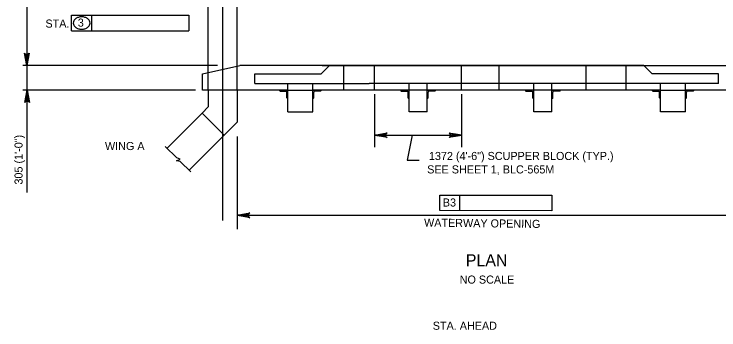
# Model space of a CAD drawing. Extents: x 638268 to 640277, y 295465 to 298435.
# Drawn here: x 638489.1 to 638751, y 297540.7 to 297658 of the extents above; entities that cross this region are included whole.
import ezdxf

# ---------------------------------------------------------------- set-up
doc = ezdxf.new("R2010")
doc.units = 0
for name, color, linetype in [('2', 7, 'Continuous'), ('3', 7, 'Continuous'), ('4', 7, 'Continuous')]:
    doc.layers.add(name, color=color, linetype=linetype)

msp = doc.modelspace()

# ---------------------------------------------------------------- linework, layer by layer
at = {"layer": '2'}
for p, q in [((638561.24, 297629.77), (638561.24, 297741.89)), ((638572.01, 297629.77), (638572.01, 297741.89)), ((638559.11, 297635.8), (638572.96, 297638.9)), ((638606.26, 297638.9), (638572.96, 297638.9)), ((638606.26, 297638.9), (638603.17, 297635.8)), ((638603.59, 297638.9), (638619.75, 297638.9)), ((638603.59, 297638.9), (638756.47, 297638.9)), ((638723.16, 297638.9), (638606.26, 297638.9)), ((638611.64, 297629.77), (638611.64, 297638.9)), ((638623.04, 297629.77), (638623.04, 297638.9)), ((638655.38, 297629.77), (638655.38, 297638.9)), ((638669.41, 297629.77), (638669.41, 297638.9)), ((638701.75, 297629.77), (638701.75, 297638.9)), ((638716.53, 297629.77), (638716.53, 297638.9)), ((638723.16, 297638.9), (638726.25, 297635.8)), ((638559.11, 297629.77), (638559.11, 297635.8)), ((638578.53, 297635.8), (638603.17, 297635.8)), ((638578.53, 297632.17), (638578.53, 297635.8)), ((638750.89, 297635.8), (638726.25, 297635.8)), ((638750.89, 297632.17), (638750.89, 297635.8)), ((638578.53, 297632.17), (638621.04, 297632.17)), ((638590.86, 297621.68), (638590.86, 297632.17)), ((638600.09, 297621.68), (638600.09, 297632.17)), ((638750.89, 297632.17), (638621.04, 297632.17)), ((638635.85, 297621.68), (638635.85, 297632.17)), ((638642.58, 297621.68), (638642.58, 297632.17)), ((638682.21, 297621.68), (638682.21, 297632.17)), ((638688.94, 297621.68), (638688.94, 297632.17)), ((638729.33, 297621.68), (638729.33, 297632.17)), ((638738.57, 297621.68), (638738.57, 297632.17)), ((638590.86, 297629.77), (638559.11, 297629.77)), ((638561.24, 297629.77), (638561.24, 297623.56)), ((638572.01, 297629.77), (638572.01, 297617.86)), ((638587.76, 297629.59), (638587.76, 297629.77)), ((638590.86, 297629.77), (638587.76, 297629.77)), ((638587.95, 297629.41), (638590.13, 297629.41)), ((638590.49, 297626.86), (638590.49, 297629.05)), ((638590.86, 297629.77), (638600.09, 297629.77)), ((638590.86, 297626.68), (638590.86, 297629.77)), ((638600.09, 297626.68), (638600.09, 297629.77)), ((638600.09, 297629.77), (638603.18, 297629.77)), ((638635.85, 297629.77), (638600.09, 297629.77)), ((638600.46, 297626.86), (638600.46, 297629.05)), ((638603, 297629.41), (638600.82, 297629.41)), ((638603.18, 297629.59), (638603.18, 297629.77)), ((638632.76, 297629.59), (638632.76, 297629.77)), ((638635.85, 297629.77), (638632.76, 297629.77)), ((638632.94, 297629.41), (638635.12, 297629.41)), ((638635.49, 297626.86), (638635.49, 297629.05)), ((638635.85, 297626.68), (638635.85, 297629.77)), ((638642.58, 297629.77), (638635.85, 297629.77)), ((638642.58, 297626.68), (638642.58, 297629.77)), ((638642.58, 297629.77), (638645.67, 297629.77)), ((638681, 297629.77), (638642.58, 297629.77)), ((638681, 297629.77), (638642.58, 297629.77)), ((638642.94, 297626.86), (638642.94, 297629.05)), ((638645.49, 297629.41), (638643.3, 297629.41)), ((638645.67, 297629.59), (638645.67, 297629.77)), ((638679.12, 297629.59), (638679.12, 297629.77)), ((638682.21, 297629.77), (638679.12, 297629.77)), ((638679.3, 297629.41), (638681.49, 297629.41)), ((638690.19, 297629.77), (638680.96, 297629.77)), ((638681.85, 297626.86), (638681.85, 297629.05)), ((638688.94, 297629.77), (638682.21, 297629.77)), ((638682.21, 297626.68), (638682.21, 297629.77)), ((638688.94, 297626.68), (638688.94, 297629.77)), ((638688.94, 297629.77), (638692.03, 297629.77)), ((638727.37, 297629.77), (638688.94, 297629.77)), ((638689.3, 297626.86), (638689.3, 297629.05)), ((638691.85, 297629.41), (638689.67, 297629.41)), ((638692.03, 297629.59), (638692.03, 297629.77)), ((638726.24, 297629.59), (638726.24, 297629.77)), ((638729.33, 297629.77), (638726.24, 297629.77)), ((638726.42, 297629.41), (638728.61, 297629.41)), ((638728.97, 297626.86), (638728.97, 297629.05)), ((638729.33, 297626.68), (638729.33, 297629.77)), ((638729.33, 297629.77), (638738.57, 297629.77)), ((638738.57, 297626.68), (638738.57, 297629.77)), ((638738.57, 297629.77), (638741.66, 297629.77)), ((638770.31, 297629.77), (638738.57, 297629.77)), ((638738.93, 297626.86), (638738.93, 297629.05)), ((638741.48, 297629.41), (638739.3, 297629.41)), ((638741.66, 297629.59), (638741.66, 297629.77)), ((638590.67, 297626.68), (638590.86, 297626.68)), ((638600.27, 297626.68), (638600.09, 297626.68)), ((638635.67, 297626.68), (638635.85, 297626.68)), ((638642.76, 297626.68), (638642.58, 297626.68)), ((638682.03, 297626.68), (638682.21, 297626.68)), ((638689.12, 297626.68), (638688.94, 297626.68)), ((638729.15, 297626.68), (638729.33, 297626.68)), ((638738.75, 297626.68), (638738.57, 297626.68)), ((638561.24, 297623.56), (638558.93, 297621.25)), ((638558.93, 297621.25), (638545.91, 297608.23)), ((638558.93, 297621.25), (638567.16, 297613.02)), ((638590.86, 297621.68), (638600.09, 297621.68)), ((638642.58, 297621.68), (638635.85, 297621.68)), ((638688.94, 297621.68), (638682.21, 297621.68)), ((638688.94, 297621.68), (638682.21, 297621.68)), ((638738.57, 297621.68), (638729.33, 297621.68)), ((638572.01, 297617.86), (638554.14, 297600))]:
    msp.add_line(p, q, dxfattribs=at)
for centre, radius, start, end in [((638587.95, 297629.59), 0.182, 180.0016, 270), ((638590.13, 297629.05), 0.364, 0.0016, 90), ((638600.82, 297629.05), 0.364, 90, 179.9984), ((638603, 297629.59), 0.182, 270, 359.9984), ((638632.94, 297629.59), 0.182, 180.0016, 270), ((638635.12, 297629.05), 0.364, 0.0016, 90), ((638643.3, 297629.05), 0.364, 90, 179.9984), ((638645.49, 297629.59), 0.182, 270, 359.9984), ((638679.3, 297629.59), 0.182, 180.0016, 270), ((638681.49, 297629.05), 0.364, 0.0016, 90), ((638689.67, 297629.05), 0.364, 90, 179.9984), ((638691.85, 297629.59), 0.182, 270, 359.9984), ((638726.42, 297629.59), 0.182, 180.0016, 270), ((638728.61, 297629.05), 0.364, 0.0016, 90), ((638739.3, 297629.05), 0.364, 90, 179.9984), ((638741.48, 297629.59), 0.182, 270, 359.9984), ((638590.67, 297626.86), 0.182, 180.0016, 270), ((638600.27, 297626.86), 0.182, 270, 359.9984), ((638635.67, 297626.86), 0.182, 180.0016, 270), ((638642.76, 297626.86), 0.182, 270, 359.9984), ((638682.03, 297626.86), 0.182, 180.0016, 270), ((638689.12, 297626.86), 0.182, 270, 359.9984), ((638729.15, 297626.86), 0.182, 180.0016, 270), ((638738.75, 297626.86), 0.182, 270, 359.9984)]:
    msp.add_arc(centre, radius, start, end, dxfattribs=at)
at = {"layer": '3'}
for p, q in [((638566.62, 297581.37), (638566.62, 297801.29)), ((638545.27, 297608.86), (638549.54, 297604.59)), ((638549.46, 297603.48), (638550.85, 297604.18)), ((638550.85, 297604.18), (638549.54, 297604.59)), ((638550.81, 297603.32), (638549.46, 297603.48)), ((638550.81, 297603.32), (638554.72, 297599.41))]:
    msp.add_line(p, q, dxfattribs=at)
at = {"layer": '4'}
for p, q in [((638493.78, 297781.29), (638493.78, 297591.81)), ((638510.4, 297651.84), (638510.4, 297657.61)), ((638510.4, 297657.61), (638517.97, 297657.61)), ((638517.97, 297651.84), (638517.97, 297657.61)), ((638517.97, 297657.61), (638553.98, 297657.61)), ((638553.98, 297657.61), (638553.98, 297651.84)), ((638510.4, 297651.84), (638553.98, 297651.84)), ((638564.62, 297638.89), (638492.34, 297638.89)), ((638556.55, 297629.77), (638492.34, 297629.77)), ((638623.04, 297628.24), (638623.04, 297608.6)), ((638655.38, 297628.24), (638655.38, 297608.6)), ((638572.01, 297612.54), (638572.01, 297578.12)), ((638623.04, 297613.03), (638655.38, 297613.03)), ((638637, 297613.03), (638635.15, 297603.8)), ((638635.15, 297603.8), (638639.58, 297603.8)), ((638647.35, 297590.79), (638654.7, 297590.79)), ((638647.35, 297585.03), (638647.35, 297590.79)), ((638654.7, 297585.02), (638654.7, 297590.79)), ((638654.7, 297590.79), (638688.87, 297590.77)), ((638688.87, 297590.77), (638688.87, 297585)), ((638572.01, 297583.28), (638757, 297583.28)), ((638688.87, 297585), (638647.35, 297585.03))]:
    msp.add_line(p, q, dxfattribs=at)
for points in [[(638493.78, 297638.89), (638492.9, 297643.55), (638493.15, 297643.2), (638493.46, 297643.01), (638493.78, 297642.96), (638494.09, 297643.01), (638494.4, 297643.2), (638494.65, 297643.55), (638493.78, 297638.89), (638494.4, 297643.2), (638494.09, 297643.01), (638493.78, 297638.89), (638493.78, 297642.96), (638493.46, 297643.01), (638493.78, 297638.89), (638493.15, 297643.2)], [(638493.89, 297629.77), (638494.76, 297625.11), (638494.51, 297625.47), (638494.2, 297625.66), (638493.89, 297625.71), (638493.57, 297625.66), (638493.26, 297625.47), (638493.01, 297625.11), (638493.89, 297629.77), (638493.26, 297625.47), (638493.57, 297625.66), (638493.89, 297629.77), (638493.89, 297625.71), (638494.2, 297625.66), (638493.89, 297629.77), (638494.51, 297625.47)], [(638623.04, 297613.03), (638627.7, 297613.9), (638627.35, 297613.65), (638627.16, 297613.34), (638627.11, 297613.03), (638627.16, 297612.72), (638627.35, 297612.4), (638627.7, 297612.16), (638623.04, 297613.03), (638627.35, 297612.4), (638627.16, 297612.72), (638623.04, 297613.03), (638627.11, 297613.03), (638627.16, 297613.34), (638623.04, 297613.03), (638627.35, 297613.65)], [(638655.38, 297613.03), (638650.72, 297612.16), (638651.08, 297612.4), (638651.27, 297612.72), (638651.32, 297613.03), (638651.27, 297613.34), (638651.08, 297613.65), (638650.72, 297613.9), (638655.38, 297613.03), (638651.08, 297613.65), (638651.27, 297613.34), (638655.38, 297613.03), (638651.32, 297613.03), (638651.27, 297612.72), (638655.38, 297613.03), (638651.08, 297612.4)], [(638572.01, 297583.28), (638576.67, 297584.15), (638576.31, 297583.9), (638576.12, 297583.59), (638576.07, 297583.28), (638576.12, 297582.96), (638576.31, 297582.65), (638576.67, 297582.4), (638572.01, 297583.28), (638576.31, 297582.65), (638576.12, 297582.96), (638572.01, 297583.28), (638576.07, 297583.28), (638576.12, 297583.59), (638572.01, 297583.28), (638576.31, 297583.9)]]:
    msp.add_lwpolyline(points, dxfattribs=at)
for points in [[(638493.3, 297641.78), (638494.26, 297641.78), (638493.78, 297638.89)], [(638493.3, 297626.91), (638494.26, 297626.91), (638493.78, 297629.79)], [(638626, 297613.52), (638626, 297612.54), (638623.04, 297613.03)], [(638652.43, 297613.52), (638652.43, 297612.54), (638655.38, 297613.03)]]:
    msp.add_lwpolyline(points, close=True, dxfattribs=at)
for centre, radius, start, end in [((638513.89, 297653.7), 3.23, 106.9552, 126.3544), ((638514.18, 297652.75), 4.22, 90, 106.9552), ((638514.18, 297652.75), 4.22, 73.0448, 90), ((638514.47, 297653.7), 3.23, 53.6456, 73.0448), ((638512.77, 297654.68), 1.71, 150.6308, 180), ((638512.77, 297654.68), 1.71, 180, 209.3692), ((638513.45, 297654.3), 2.49, 126.3544, 150.6308), ((638513.45, 297655.06), 2.49, 209.3692, 233.6456), ((638514.91, 297654.3), 2.49, 29.3692, 53.6456), ((638514.91, 297655.06), 2.49, 306.3544, 330.6308), ((638515.59, 297654.68), 1.71, 0, 29.3692), ((638515.59, 297654.68), 1.71, 330.6308, 0), ((638513.89, 297655.66), 3.23, 233.6456, 253.0448), ((638514.18, 297656.6), 4.22, 253.0448, 270), ((638514.18, 297656.6), 4.22, 270, 286.9552), ((638514.47, 297655.66), 3.23, 286.9552, 306.3544)]:
    msp.add_arc(centre, radius, start, end, dxfattribs=at)

# ---------------------------------------------------------------- texts
for s, height, p in [('3', 3, (638512.73, 297653.33)), ('STA.', 3, (638500.72, 297652.98)), ('WING A', 3, (638522.84, 297607.51)), ('1372 (4\'-6") SCUPPER BLOCK (TYP.)', 3, (638643.25, 297603.82)), ('SEE SHEET 1, BLC-565M', 3, (638642.61, 297598.83)), ('PLAN', 4.429, (638656.96, 297564.4)), ('NO SCALE', 3, (638654.69, 297557.92)), ('STA. AHEAD', 3, (638644.68, 297540.79))]:
    msp.add_text(s, height=height, dxfattribs=at).set_placement(p)
for s, rotation, p in [('305 (1\'-0")', 90, (638492.22, 297594.7)), ('B3', 359.9692, (638648.42, 297586.55)), ('WATERWAY OPENING', 359.308, (638641.42, 297579.1))]:
    msp.add_text(s, height=3, rotation=rotation, dxfattribs=at).set_placement(p)

doc.saveas('drawing.dxf')
